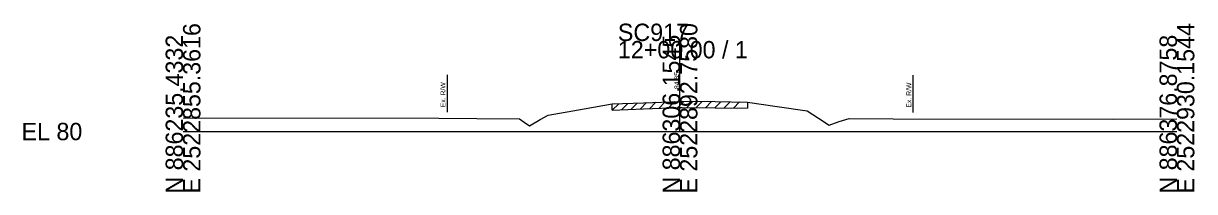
# Model space of a CAD drawing. Extents: x -26 to 218, y -10 to 12021.
# Drawn here: x -25.7 to 162.8, y 9990.3 to 10017.4 of the extents above; entities that cross this region are included whole.
import ezdxf

# ---------------------------------------------------------------- set-up
doc = ezdxf.new("R2010")
doc.units = 0
for name, color, linetype in [('RD_GPK_XS_Cell', 7, 'Continuous'), ('RD_XS_ExGround', 7, 'Continuous'), ('RD_XS_ExPaveRet', 7, 'Continuous'), ('RD_XS_ExRW', 7, 'Continuous'), ('RD_XS_TX_Elev_EX', 7, 'Continuous')]:
    doc.layers.add(name, color=color, linetype=linetype)

msp = doc.modelspace()

# ---------------------------------------------------------------- linework, layer by layer
at = {"layer": 'RD_GPK_XS_Cell'}
for p, q in [((80, 10000), (80, 10014.6)), ((0, 10000), (80, 10000)), ((80, 10000), (160, 10000))]:
    msp.add_line(p, q, dxfattribs=at)
at = {"layer": 'RD_XS_ExGround'}
for p, q in [((58.76, 10002.64), (64.59, 10003.65)), ((64.59, 10003.65), (69.09, 10004.44)), ((69.09, 10004.44), (74.11, 10004.64)), ((74.11, 10004.64), (80, 10004.85)), ((80, 10004.85), (80.37, 10004.87)), ((80.37, 10004.87), (85.65, 10004.82)), ((85.65, 10004.82), (90.87, 10004.76)), ((90.87, 10004.76), (95.67, 10004.01)), ((95.67, 10004.01), (100.5, 10003.31)), ((0, 10002.19), (41.19, 10002.13)), ((41.19, 10002.13), (47.3, 10002.1)), ((47.3, 10002.1), (54.17, 10002.05)), ((54.17, 10002.05), (54.92, 10001.51)), ((55.75, 10000.91), (57.5, 10001.95)), ((57.5, 10001.95), (58.76, 10002.64)), ((100.5, 10003.31), (102.31, 10002.16)), ((102.31, 10002.16), (104.03, 10001.01)), ((105.61, 10001.6), (107.23, 10002.11)), ((107.23, 10002.11), (114.32, 10002.07)), ((114.32, 10002.07), (149.86, 10002)), ((149.86, 10002), (160, 10002.04)), ((54.92, 10001.51), (55.75, 10000.91)), ((104.03, 10001.01), (105.61, 10001.6))]:
    msp.add_line(p, q, dxfattribs=at)
at = {"layer": 'RD_XS_ExPaveRet'}
for p, q in [((69.09, 10003.44), (70.13, 10004.48)), ((69.09, 10003.44), (69.09, 10004.44)), ((69.09, 10003.44), (74.11, 10003.64)), ((70.59, 10003.5), (71.63, 10004.54)), ((72.09, 10003.56), (73.13, 10004.6)), ((73.59, 10003.62), (74.63, 10004.66)), ((74.11, 10003.64), (80, 10003.85)), ((75.09, 10003.68), (76.13, 10004.71)), ((76.59, 10003.73), (77.63, 10004.77)), ((78.09, 10003.78), (79.13, 10004.82)), ((79.59, 10003.84), (80.61, 10004.86)), ((80, 10003.85), (80.37, 10003.87)), ((80.37, 10003.87), (85.65, 10003.82)), ((81.09, 10003.86), (82.08, 10004.85)), ((82.59, 10003.85), (83.58, 10004.84)), ((84.09, 10003.83), (85.08, 10004.82)), ((85.59, 10003.82), (86.58, 10004.81)), ((85.65, 10003.82), (90.87, 10003.76)), ((87.09, 10003.8), (88.08, 10004.79)), ((88.59, 10003.79), (89.58, 10004.78)), ((90.87, 10004.76), (90.87, 10003.76))]:
    msp.add_line(p, q, dxfattribs=at)
at = {"layer": 'RD_XS_ExRW'}
for p, q in [((42.5, 10009.13), (42.5, 10003.13)), ((117.5, 10009.07), (117.5, 10003.07)), ((117.5, 10009.07), (117.5, 10003.07))]:
    msp.add_line(p, q, dxfattribs=at)

# ---------------------------------------------------------------- texts
at = {"layer": 'RD_GPK_XS_Cell'}
for s, p in [('E 2522855.3616', (2.8, 9990)), ('E 2522892.7580', (82.8, 9990)), ('E 2522930.1544', (162.8, 9990)), ('N 886235.4332', (0, 9990)), ('N 886306.1545', (80, 9990)), ('N 886376.8758', (160, 9990))]:
    msp.add_text(s, height=2.8, rotation=90, dxfattribs=at).set_placement(p)
for s, p in [('SC917', (70, 10014.6)), ('12+00.00 / 1', (70, 10011.8)), ('EL 80', (-26, 9998.6))]:
    msp.add_text(s, height=2.8, dxfattribs=at).set_placement(p)
at = {"layer": 'RD_XS_ExRW'}
for p in [(42.25, 10003.91), (117.25, 10003.85), (117.25, 10003.85)]:
    msp.add_text('Ex. R/W ', height=0.8, rotation=90, dxfattribs=at).set_placement(p)
at = {"layer": 'RD_XS_TX_Elev_EX'}
msp.add_text('84.85', height=0.8, rotation=90, dxfattribs=at).set_placement((79.9, 10006.85))

doc.saveas('drawing.dxf')
